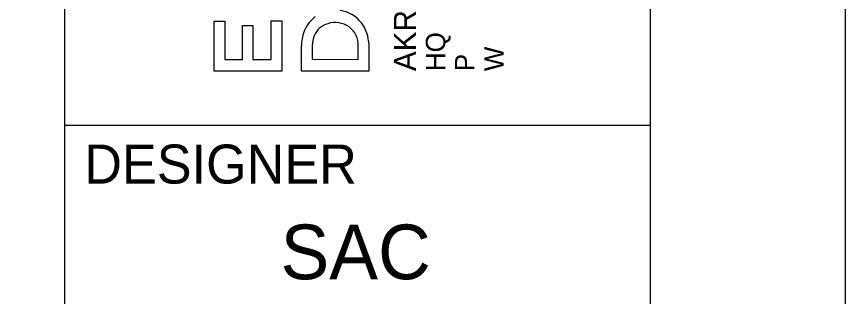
# Model space of a CAD drawing. Extents: x 0 to 34, y 0 to 22.
# Drawn here: x 31.877 to 34, y 2.061 to 2.778 of the extents above; entities that cross this region are included whole.
import ezdxf

# ---------------------------------------------------------------- set-up
doc = ezdxf.new("R2010")
doc.units = 0
for name, color, linetype in [('SH_Border', 7, 'Continuous'), ('SH_Cut_Line', 7, 'Continuous'), ('SH_Data', 7, 'Continuous')]:
    doc.layers.add(name, color=color, linetype=linetype)

msp = doc.modelspace()

# ---------------------------------------------------------------- linework, layer by layer
at = {"layer": 'SH_Border'}
for p, q in [((32, 0.5), (32, 21.5)), ((32, 2.5), (33.5, 2.5))]:
    msp.add_line(p, q, dxfattribs=at)
msp.add_lwpolyline([(1.5, 21.5), (33.5, 21.5), (33.5, 0.5), (1.5, 0.5)], close=True, dxfattribs=at)
at = {"layer": 'SH_Cut_Line'}
msp.add_lwpolyline([(0, 0), (34, 0), (34, 22), (0, 22)], close=True, dxfattribs=at)
at = {"layer": 'SH_Data'}
for p, q in [((32.383, 2.6379), (32.383, 2.766)), ((32.383, 2.766), (32.4101, 2.766)), ((32.4101, 2.766), (32.4101, 2.6683)), ((32.5286, 2.6683), (32.5286, 2.7672)), ((32.5286, 2.7672), (32.5557, 2.7672)), ((32.5557, 2.7672), (32.5557, 2.6379)), ((32.455, 2.6683), (32.455, 2.7549)), ((32.455, 2.7549), (32.4822, 2.7549)), ((32.4822, 2.7549), (32.4822, 2.6683)), ((32.6064, 2.638), (32.6064, 2.704)), ((32.6347, 2.7118), (32.6341, 2.7023)), ((32.6341, 2.7023), (32.6341, 2.6684)), ((32.7515, 2.6683), (32.7515, 2.7024)), ((32.7785, 2.715), (32.7792, 2.7021)), ((32.7792, 2.7021), (32.7792, 2.638)), ((32.4101, 2.6683), (32.455, 2.6683)), ((32.4822, 2.6683), (32.5286, 2.6683)), ((32.6341, 2.6684), (32.7515, 2.6683)), ((32.5557, 2.6379), (32.383, 2.6379)), ((32.7792, 2.638), (32.6064, 2.638))]:
    msp.add_line(p, q, dxfattribs=at)
msp.add_lwpolyline([(32.383, 2.6379), (32.383, 2.766), (32.4101, 2.766), (32.4101, 2.6683), (32.455, 2.6683), (32.455, 2.7549), (32.4822, 2.7549), (32.4822, 2.6683), (32.5286, 2.6683), (32.5286, 2.7672), (32.5557, 2.7672), (32.5557, 2.6379)], close=True, dxfattribs=at)
for points in [[(32.7785, 2.715), (32.7792, 2.7021), (32.7792, 2.638), (32.6064, 2.638)], [(32.6064, 2.638), (32.6064, 2.704)], [(32.6347, 2.7118), (32.6341, 2.7023), (32.6341, 2.6684), (32.7515, 2.6683), (32.7515, 2.7024)]]:
    msp.add_lwpolyline(points, dxfattribs=at)
for centre, radius, start, end in [((32.6946, 2.7113), 0.0827, 37.8521, 82.402), ((32.6946, 2.7113), 0.0827, 37.8521, 82.402), ((32.6939, 2.7089), 0.0865, 127.2362, 165.148), ((32.6939, 2.7089), 0.0865, 127.2362, 165.148), ((32.6928, 2.6986), 0.0639, 55.6727, 107.2093), ((32.6928, 2.6986), 0.0639, 55.6727, 107.2093), ((32.6859, 2.7057), 0.0931, 5.7333, 37.304), ((32.6859, 2.7057), 0.0931, 5.7333, 37.304), ((32.6889, 2.7078), 0.054, 106.1881, 157.3861), ((32.6889, 2.7078), 0.054, 106.1881, 157.3861), ((32.6929, 2.705), 0.0587, 357.4662, 52.2665), ((32.6929, 2.705), 0.0587, 357.4662, 52.2665), ((32.7143, 2.7028), 0.1078, 164.7861, 179.3704), ((32.7143, 2.7028), 0.1078, 164.7861, 179.3704), ((32.6983, 2.7039), 0.0641, 157.3571, 172.9275), ((32.6983, 2.7039), 0.0641, 157.3571, 172.9275)]:
    msp.add_arc(centre, radius, start, end, dxfattribs=at)

# ---------------------------------------------------------------- texts
for s, height, p in [('AKRON / CLEVELAND / COLUMBUS', 0.056969, (32.9001, 2.638)), ('HQ ', 0.04985, (32.9749, 2.638)), ('W', 0.0498, (33.1244, 2.638)), ('P', 0.0498, (33.0497, 2.638))]:
    msp.add_text(s, height=height, rotation=90, dxfattribs=at).set_placement(p)
for s, height, p in [('DESIGNER', 0.1, (32.05, 2.35)), ('SAC', 0.14, (32.5528, 2.105))]:
    msp.add_text(s, height=height, dxfattribs=at).set_placement(p)

doc.saveas('drawing.dxf')
